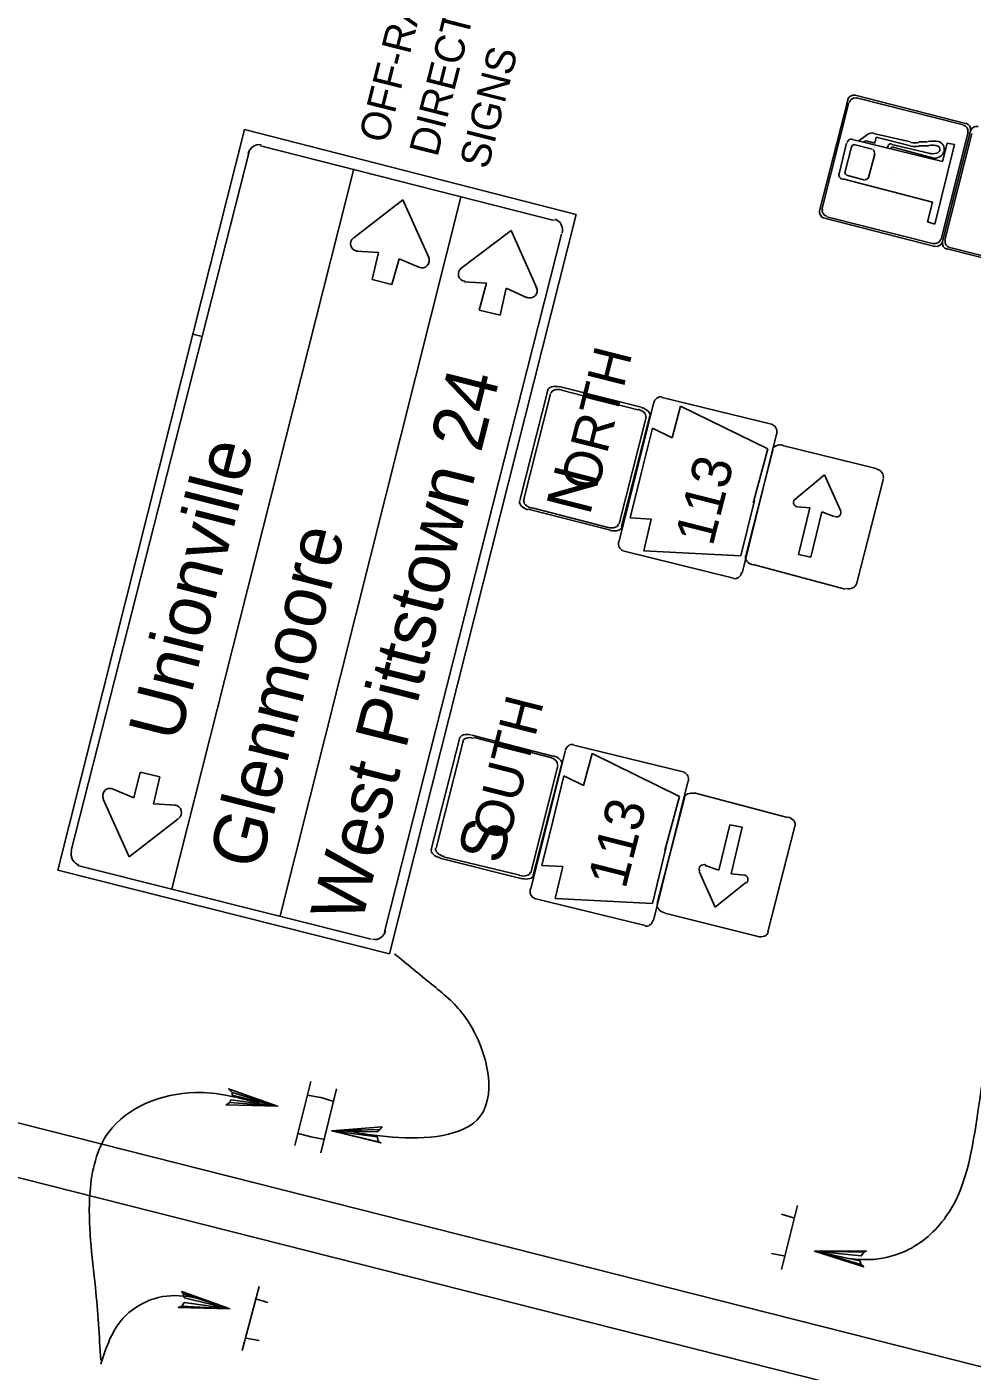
# Model space of a CAD drawing. Extents: x 644898 to 648326, y 298294 to 300670.
# Drawn here: x 647042.6 to 647138.7, y 300455.8 to 300592.6 of the extents above; entities that cross this region are included whole.
import ezdxf

# ---------------------------------------------------------------- set-up
doc = ezdxf.new("R2010")
doc.units = 0
doc.layers.add('2', color=7, linetype='Continuous')

msp = doc.modelspace()

# ---------------------------------------------------------------- linework, layer by layer
at = {"layer": '2'}
for p, q in [((647123.2, 300573.87), (647126.07, 300585.12)), ((647123.45, 300573.99), (647126.2, 300584.87)), ((647126.82, 300585.62), (647138.07, 300582.74)), ((647126.95, 300585.37), (647137.82, 300582.62)), ((647059.45, 300561.3), (647064.7, 300582.12)), ((647064.7, 300582.12), (647098.45, 300573.49)), ((647125.2, 300577.62), (647125.95, 300580.74)), ((647135.7, 300578.87), (647126.57, 300581.12)), ((647127.2, 300580.99), (647128.07, 300581.62)), ((647127.95, 300580.99), (647127.7, 300580.87)), ((647128.82, 300580.74), (647127.95, 300580.99)), ((647128.7, 300581.74), (647132.45, 300580.87)), ((647128.95, 300581.37), (647128.82, 300580.74)), ((647128.95, 300581.37), (647132.45, 300580.49)), ((647133.32, 300580.87), (647134.2, 300580.87)), ((647138.32, 300581.87), (647135.57, 300570.99)), ((647138.57, 300581.99), (647135.7, 300570.74)), ((647135.7, 300570.74), (647138.57, 300581.99)), ((647135.7, 300578.87), (647136.2, 300580.74)), ((647135.95, 300570.87), (647138.7, 300581.74)), ((647136.95, 300580.62), (647136.2, 300580.74)), ((647065.2, 300579.99), (647060.38, 300561.06)), ((647096.2, 300572.87), (647066.32, 300580.49)), ((647125.82, 300577.87), (647126.45, 300580.37)), ((647128.57, 300580.12), (647126.7, 300580.62)), ((647128.2, 300577.24), (647128.82, 300579.62)), ((647130.07, 300580.24), (647130.2, 300580.49)), ((647130.45, 300580.12), (647130.45, 300580.24)), ((647130.57, 300580.62), (647134.32, 300579.74)), ((647130.57, 300580.37), (647134.7, 300579.24)), ((647133.32, 300580.49), (647134.32, 300580.49)), ((647134.95, 300572.49), (647136.95, 300580.62)), ((647057.32, 300504.87), (647075.82, 300578.12)), ((647134.7, 300574.74), (647125.57, 300577.12)), ((647127.82, 300576.99), (647125.95, 300577.49)), ((647130.95, 300577.99), (647130.95, 300577.99)), ((647068.32, 300502.12), (647086.7, 300575.24)), ((647075.82, 300571.12), (647080.82, 300574.99)), ((647080.82, 300574.99), (647083.45, 300569.12)), ((647134.2, 300572.74), (647134.7, 300574.74)), ((647098.45, 300573.49), (647079.45, 300498.24)), ((647134.95, 300570.24), (647123.7, 300573.12)), ((647134.82, 300570.49), (647123.95, 300573.24)), ((647134.95, 300572.49), (647134.2, 300572.74)), ((647078.95, 300500.49), (647096.95, 300571.49)), ((647086.7, 300567.99), (647091.82, 300571.87)), ((647091.82, 300571.87), (647094.45, 300565.99)), ((647147.45, 300567.12), (647136.2, 300569.99)), ((647147.32, 300567.37), (647136.45, 300570.12)), ((647078.32, 300569.62), (647076.07, 300569.74)), ((647077.7, 300566.87), (647078.32, 300569.62)), ((647080.45, 300568.99), (647079.7, 300566.37)), ((647082.45, 300568.12), (647080.45, 300568.99)), ((647079.7, 300566.37), (647077.7, 300566.87)), ((647089.32, 300566.49), (647087.07, 300566.62)), ((647088.57, 300563.74), (647089.32, 300566.49)), ((647091.32, 300565.99), (647090.7, 300563.24)), ((647093.45, 300564.99), (647091.32, 300565.99)), ((647090.7, 300563.24), (647088.57, 300563.74)), ((647045.7, 300506.74), (647059.45, 300561.3)), ((647060.38, 300561.06), (647047.07, 300508.74)), ((647060.38, 300561.06), (647059.45, 300561.3)), ((647059.45, 300561.3), (647060.38, 300561.06)), ((647092.7, 300544.37), (647095.57, 300555.62)), ((647093.07, 300544.37), (647095.82, 300555.24)), ((647096.7, 300555.99), (647105.07, 300553.87)), ((647096.95, 300555.62), (647104.7, 300553.62)), ((647107.2, 300554.87), (647118.45, 300552.12)), ((647102.82, 300540.24), (647106.32, 300554.24)), ((647109.07, 300553.99), (647108.2, 300550.74)), ((647117.95, 300549.62), (647109.07, 300553.99)), ((647105.57, 300552.87), (647102.82, 300541.99)), ((647105.95, 300552.99), (647103.07, 300541.74)), ((647106.2, 300551.74), (647105.07, 300547.12)), ((647108.2, 300550.74), (647106.2, 300551.74)), ((647118.82, 300551.12), (647115.32, 300536.99)), ((647115.7, 300538.74), (647118.45, 300549.49)), ((647115.7, 300538.74), (647118.45, 300549.49)), ((647115.7, 300538.74), (647118.45, 300549.49)), ((647116.45, 300544.12), (647117.95, 300549.62)), ((647119.45, 300549.99), (647128.95, 300547.62)), ((647119.45, 300549.99), (647128.95, 300547.62)), ((647119.45, 300549.99), (647128.95, 300547.62)), ((647099.32, 300548.62), (647099.32, 300548.62)), ((647105.07, 300547.12), (647103.95, 300542.62)), ((647120.7, 300544.49), (647123.7, 300546.99)), ((647123.7, 300546.99), (647125.32, 300543.37)), ((647129.7, 300546.62), (647126.95, 300535.87)), ((647129.7, 300546.62), (647126.95, 300535.87)), ((647129.7, 300546.62), (647126.95, 300535.87)), ((647115.2, 300538.74), (647116.57, 300544.37)), ((647101.95, 300541.37), (647093.57, 300543.49)), ((647101.7, 300541.62), (647093.95, 300543.62)), ((647103.95, 300542.62), (647106.07, 300542.49)), ((647106.07, 300542.49), (647105.32, 300539.24)), ((647122.2, 300543.62), (647120.95, 300543.74)), ((647121.07, 300538.87), (647122.2, 300543.62)), ((647123.45, 300543.24), (647122.32, 300538.62)), ((647122.7, 300542.74), (647122.7, 300542.74)), ((647122.7, 300542.74), (647122.7, 300542.74)), ((647122.7, 300542.74), (647122.7, 300542.74)), ((647124.7, 300542.74), (647123.45, 300543.24)), ((647114.45, 300536.49), (647103.2, 300539.24)), ((647105.32, 300539.24), (647115.2, 300538.74)), ((647122.32, 300538.62), (647121.07, 300538.87)), ((647065.57, 300537.24), (647065.57, 300537.24)), ((647125.82, 300535.37), (647116.45, 300537.87)), ((647125.82, 300535.37), (647116.45, 300537.87)), ((647125.82, 300535.37), (647116.45, 300537.87)), ((647114.45, 300536.49), (647114.45, 300536.49)), ((647076.45, 300534.49), (647076.45, 300534.49)), ((647076.45, 300534.49), (647076.45, 300534.49)), ((647076.32, 300531.62), (647076.32, 300531.62)), ((647087.2, 300528.87), (647087.2, 300528.87)), ((647087.2, 300528.87), (647087.2, 300528.87)), ((647083.7, 300508.87), (647086.57, 300520.12)), ((647084.2, 300508.99), (647086.95, 300519.87)), ((647087.82, 300520.49), (647096.07, 300518.37)), ((647088.07, 300520.24), (647095.7, 300518.24)), ((647098.2, 300519.49), (647109.45, 300516.74)), ((647093.82, 300504.87), (647097.32, 300518.87)), ((647100.07, 300518.62), (647099.2, 300515.37)), ((647108.95, 300514.24), (647100.07, 300518.62)), ((647053.45, 300514.12), (647054.07, 300516.74)), ((647054.07, 300516.74), (647053.45, 300514.12)), ((647054.07, 300516.74), (647056.07, 300516.24)), ((647056.07, 300516.24), (647054.07, 300516.74)), ((647096.57, 300517.37), (647093.82, 300506.49)), ((647096.95, 300517.49), (647094.07, 300506.24)), ((647056.07, 300516.24), (647055.45, 300513.49)), ((647055.45, 300513.49), (647056.07, 300516.24)), ((647097.2, 300516.37), (647096.07, 300511.74)), ((647099.2, 300515.37), (647097.2, 300516.37)), ((647109.82, 300515.74), (647106.32, 300501.62)), ((647052.95, 300508.12), (647050.32, 300513.99)), ((647050.32, 300513.99), (647052.95, 300508.12)), ((647051.32, 300514.99), (647053.45, 300514.12)), ((647053.45, 300514.12), (647051.32, 300514.99)), ((647106.7, 300503.37), (647109.45, 300514.12)), ((647106.7, 300503.37), (647109.45, 300514.12)), ((647106.7, 300503.37), (647109.45, 300514.12)), ((647107.45, 300508.74), (647108.95, 300514.24)), ((647110.45, 300514.62), (647119.95, 300512.12)), ((647110.45, 300514.62), (647119.95, 300512.12)), ((647110.45, 300514.62), (647119.95, 300512.12)), ((647055.45, 300513.49), (647057.7, 300513.37)), ((647057.7, 300513.37), (647055.45, 300513.49)), ((647057.57, 300513.37), (647057.7, 300513.37)), ((647090.32, 300513.24), (647090.32, 300513.24)), ((647057.95, 300511.99), (647052.95, 300508.12)), ((647052.95, 300508.12), (647057.95, 300511.99)), ((647096.07, 300511.74), (647094.95, 300507.24)), ((647114.07, 300511.37), (647112.95, 300506.74)), ((647115.32, 300511.12), (647114.07, 300511.37)), ((647114.2, 300506.37), (647115.32, 300511.12)), ((647120.7, 300511.24), (647117.95, 300500.49)), ((647120.7, 300511.24), (647117.95, 300500.49)), ((647120.7, 300511.24), (647117.95, 300500.49)), ((647101.82, 300510.24), (647101.82, 300510.24)), ((647101.82, 300510.24), (647101.82, 300510.24)), ((647106.2, 300503.37), (647107.57, 300508.99)), ((647047.7, 300507.24), (647077.57, 300499.74)), ((647092.95, 300505.87), (647084.57, 300507.99)), ((647092.7, 300506.24), (647084.95, 300508.12)), ((647094.95, 300507.24), (647097.07, 300507.12)), ((647097.07, 300507.12), (647096.32, 300503.87)), ((647112.95, 300506.74), (647111.57, 300507.24)), ((647113.7, 300507.24), (647113.7, 300507.24)), ((647113.7, 300507.24), (647113.7, 300507.24)), ((647079.45, 300498.24), (647045.7, 300506.74)), ((647110.95, 300506.62), (647112.57, 300502.99)), ((647115.57, 300506.24), (647114.2, 300506.37)), ((647112.57, 300502.99), (647115.7, 300505.49)), ((647105.45, 300501.12), (647094.2, 300503.87)), ((647096.32, 300503.87), (647106.2, 300503.37)), ((647116.95, 300499.99), (647107.45, 300502.37)), ((647116.95, 300499.99), (647107.45, 300502.37)), ((647116.95, 300499.99), (647107.45, 300502.37)), ((647105.45, 300501.12), (647105.45, 300501.12)), ((647148.82, 300453.87), (647003.32, 300490.74)), ((647069.82, 300478.74), (647071.45, 300485.24)), ((647071.07, 300483.87), (647072.45, 300483.62)), ((647074.07, 300484.49), (647072.45, 300477.99)), ((647073.7, 300483.24), (647072.45, 300483.62)), ((647188.82, 300438.24), (647014.82, 300482.24)), ((647070.07, 300479.99), (647071.45, 300479.62)), ((647072.7, 300479.37), (647071.45, 300479.62)), ((647120.95, 300472.62), (647119.32, 300466.12)), ((647120.57, 300471.37), (647119.32, 300471.74)), ((647119.57, 300467.49), (647118.32, 300467.74)), ((647066.2, 300464.37), (647064.45, 300457.87)), ((647065.82, 300463.12), (647067.07, 300462.74)), ((647064.82, 300459.12), (647066.2, 300458.87))]:
    msp.add_line(p, q, dxfattribs=at)
for points in [[(647063.45, 300484.12), (647063.45, 300483.87), (647068.07, 300482.74), (647063.45, 300484.12), (647063.07, 300484.49), (647068.07, 300482.74), (647063.32, 300483.37), (647063.2, 300483.12), (647068.07, 300482.74), (647062.82, 300482.87), (647063.2, 300483.12)], [(647078.32, 300479.12), (647078.2, 300479.62), (647073.57, 300480.24), (647078.32, 300479.12), (647078.57, 300478.99), (647073.57, 300480.24), (647078.2, 300480.12), (647078.45, 300480.37), (647073.57, 300480.24), (647078.7, 300480.62), (647078.45, 300480.37)], [(647127.45, 300466.62), (647127.32, 300466.99), (647122.7, 300467.99), (647127.45, 300466.62), (647127.7, 300466.37), (647122.7, 300467.99), (647127.45, 300467.49), (647127.7, 300467.87), (647122.7, 300467.99), (647127.95, 300467.99), (647127.7, 300467.87)], [(647058.45, 300463.62), (647058.57, 300463.24), (647063.2, 300462.12), (647058.45, 300463.62), (647058.32, 300463.87), (647063.2, 300462.12), (647058.57, 300462.74), (647058.32, 300462.37), (647063.2, 300462.12), (647057.95, 300462.24), (647058.32, 300462.37)]]:
    msp.add_lwpolyline(points, dxfattribs=at)
for centre, radius, start, end in [((647126.69, 300584.99), 0.645, 75.7754, 165.7754), ((647126.83, 300584.76), 0.597, 75.7754, 165.7754), ((647137.71, 300582), 0.597, 345.7754, 75.7754), ((647137.94, 300582.14), 0.645, 345.7754, 75.7754), ((647139.19, 300581.82), 0.645, 75.7754, 165.7754), ((647126.47, 300580.67), 0.486, 83.6778, 164.7031), ((647128.59, 300580.79), 0.991, 81.3158, 122.9841), ((647132.9, 300583.76), 2.98, 262.3862, 278.0519), ((647134.78, 300578.28), 2.68, 78.1727, 101.1253), ((647135.06, 300580.11), 0.84, 344.9893, 71.1198), ((647126.71, 300580.3), 0.274, 92.8615, 169.1523), ((647128.41, 300579.75), 0.392, 341.4902, 59.3145), ((647130.46, 300580.37), 0.318, 75.201, 153.6335), ((647130.54, 300580.24), 0.0771, 64.9719, 167.615), ((647132.9, 300583.76), 3.35, 262.3862, 278.0519), ((647134.67, 300578.96), 1.59, 68.02, 103.4387), ((647134.71, 300581.2), 1.53, 256.8807, 285.2561), ((647134.96, 300580.18), 0.953, 254.9902, 342.4176), ((647135.07, 300580.11), 0.381, 275.7441, 58.872), ((647125.59, 300577.5), 0.415, 157.4008, 262.3628), ((647126.03, 300577.75), 0.249, 154.0614, 244.0323), ((647127.88, 300577.35), 0.314, 262.0164, 342.4308), ((647124.07, 300573.88), 0.597, 165.7754, 255.7754), ((647123.84, 300573.74), 0.645, 165.7754, 255.7754), ((647076.23, 300570.5), 0.745, 125.638, 266.3035), ((647134.95, 300571.12), 0.597, 255.7754, 345.7754), ((647135.09, 300570.88), 0.645, 255.7754, 345.7754), ((647136.34, 300570.57), 0.645, 165.7754, 255.7754), ((647136.57, 300570.71), 0.597, 165.7754, 255.7754), ((647082.76, 300568.8), 0.745, 244.0264, 27.9331), ((647087.2, 300567.43), 0.745, 125.638, 266.3035), ((647093.73, 300565.73), 0.745, 244.0264, 27.9331), ((647121, 300544.19), 0.45, 126.1169, 265.3481), ((647124.93, 300543.16), 0.45, 247.2918, 24.1455), ((647051.02, 300514.33), 0.745, 64.0264, 207.9331), ((647051.02, 300514.33), 0.745, 64.0264, 207.9331), ((647057.55, 300512.63), 0.745, 305.638, 86.3035), ((647057.55, 300512.63), 0.745, 305.638, 86.3035), ((647111.42, 300506.86), 0.46, 64.0256, 207.9322), ((647115.46, 300505.81), 0.46, 305.6371, 86.3026)]:
    msp.add_arc(centre, radius, start, end, dxfattribs=at)
for centre, major_axis, ratio, start_param, end_param in [((647066.1, 300579.41), (-0.29, -1.16), 0.890186, 3.141593, 4.712389), ((647095.98, 300571.84), (0.29, 1.16), 0.890186, 4.712389, 6.283185), ((647096.58, 300555.32), (-1.04, 0.26), 0.6, 4.712389, 6.283185), ((647096.84, 300555.05), (-0.964, 0.244), 0.6, 4.712389, 6.283185), ((647106.96, 300554.13), (-0.198, -0.782), 0.8, 3.141593, 4.712389), ((647104.56, 300553.1), (-0.964, 0.244), 0.6, 3.141593, 4.712389), ((647104.92, 300553.21), (-1.04, 0.26), 0.6, 3.141593, 4.712389), ((647118.22, 300551.28), (0.198, 0.782), 0.8, 4.712389, 6.283185), ((647119.31, 300549.3), (-0.903, 0.229), 0.769266, 4.712389, 6.283185), ((647119.31, 300549.3), (-0.903, 0.229), 0.769266, 4.712389, 6.283185), ((647119.31, 300549.3), (-0.903, 0.229), 0.769266, 4.712389, 6.283185), ((647128.79, 300546.9), (-0.903, 0.229), 0.769266, 3.141593, 4.712389), ((647128.79, 300546.9), (-0.903, 0.229), 0.769266, 3.141593, 4.712389), ((647128.79, 300546.9), (-0.903, 0.229), 0.769266, 3.141593, 4.712389), ((647093.73, 300544.06), (1.04, -0.26), 0.6, 3.141593, 4.712389), ((647094.08, 300544.17), (0.964, -0.244), 0.6, 3.141593, 4.712389), ((647101.8, 300542.21), (0.964, -0.244), 0.6, 4.712389, 6.283185), ((647102.07, 300541.95), (1.04, -0.26), 0.6, 4.712389, 6.283185), ((647103.4, 300540.07), (-0.198, -0.782), 0.8, 4.712389, 6.283185), ((647116.58, 300538.53), (0.903, -0.229), 0.769266, 3.141593, 4.712389), ((647116.58, 300538.53), (0.903, -0.229), 0.769266, 3.141593, 4.712389), ((647116.58, 300538.53), (0.903, -0.229), 0.769266, 3.141593, 4.712389), ((647114.65, 300537.21), (0.198, 0.782), 0.8, 3.141593, 4.712389), ((647126.06, 300536.13), (0.903, -0.229), 0.769266, 4.712389, 6.283185), ((647126.06, 300536.13), (0.903, -0.229), 0.769266, 4.712389, 6.283185), ((647126.06, 300536.13), (0.903, -0.229), 0.769266, 4.712389, 6.283185), ((647087.6, 300519.89), (-1.04, 0.26), 0.6, 4.712389, 6.283185), ((647087.86, 300519.62), (-0.964, 0.244), 0.6, 4.712389, 6.283185), ((647097.96, 300518.76), (-0.198, -0.782), 0.8, 3.141593, 4.712389), ((647095.58, 300517.67), (-0.964, 0.244), 0.6, 3.141593, 4.712389), ((647095.94, 300517.77), (-1.04, 0.26), 0.6, 3.141593, 4.712389), ((647109.22, 300515.91), (0.198, 0.782), 0.8, 4.712389, 6.283185), ((647110.33, 300513.87), (-0.903, 0.229), 0.769266, 4.712389, 6.283185), ((647110.33, 300513.87), (-0.903, 0.229), 0.769266, 4.712389, 6.283185), ((647110.33, 300513.87), (-0.903, 0.229), 0.769266, 4.712389, 6.283185), ((647119.81, 300511.47), (-0.903, 0.229), 0.769266, 3.141593, 4.712389), ((647119.81, 300511.47), (-0.903, 0.229), 0.769266, 3.141593, 4.712389), ((647119.81, 300511.47), (-0.903, 0.229), 0.769266, 3.141593, 4.712389), ((647048.14, 300508.46), (-0.29, -1.16), 0.890186, 4.712389, 6.283185), ((647084.75, 300508.63), (1.04, -0.26), 0.6, 3.141593, 4.712389), ((647085.11, 300508.74), (0.964, -0.244), 0.6, 3.141593, 4.712389), ((647092.82, 300506.78), (0.964, -0.244), 0.6, 4.712389, 6.283185), ((647093.09, 300506.52), (1.04, -0.26), 0.6, 4.712389, 6.283185), ((647094.4, 300504.69), (-0.198, -0.782), 0.8, 4.712389, 6.283185), ((647107.6, 300503.1), (0.903, -0.229), 0.769266, 3.141593, 4.712389), ((647107.6, 300503.1), (0.903, -0.229), 0.769266, 3.141593, 4.712389), ((647107.6, 300503.1), (0.903, -0.229), 0.769266, 3.141593, 4.712389), ((647105.65, 300501.84), (0.198, 0.782), 0.8, 3.141593, 4.712389), ((647078.02, 300500.88), (0.29, 1.16), 0.890186, 3.141593, 4.712389), ((647117.08, 300500.7), (0.903, -0.229), 0.769266, 4.712389, 6.283185), ((647117.08, 300500.7), (0.903, -0.229), 0.769266, 4.712389, 6.283185), ((647117.08, 300500.7), (0.903, -0.229), 0.769266, 4.712389, 6.283185)]:
    msp.add_ellipse(centre, major_axis=major_axis, ratio=ratio, start_param=start_param, end_param=end_param, dxfattribs=at)
for points in [[(647153.07, 300562.49), (647149.57, 300528.37), (647141.82, 300497.49), (647139.2, 300481.37), (647136.07, 300471.49), (647131.95, 300467.99), (647128.2, 300467.12), (647122.7, 300467.99)], [(647079.95, 300498.24), (647083.73, 300495.15), (647087, 300492), (647088.69, 300481.71), (647079.79, 300479.59), (647074.95, 300480.24)], [(647050.07, 300456.87), (647049.53, 300464.27), (647048.98, 300474.02), (647050.86, 300480.07), (647059.63, 300484.12), (647066.23, 300483.04)], [(647050.07, 300456.49), (647052.32, 300461.12), (647056.36, 300463.35), (647063.2, 300462.12)]]:
    msp.add_spline(points, degree=3, dxfattribs=at)

# ---------------------------------------------------------------- texts
for s, height, rotation, p in [('DIRECTIONAL', 3, 75.7789, (647084.32, 300579.24)), ('OFF-RAMP', 3, 75.7789, (647079.2, 300580.62)), ('SIGNS', 3, 75.7789, (647089.45, 300577.99)), ('ORTH', 3.875, 75.7783, (647100.57, 300545.12)), ('West Pittstown 24', 5.3752, 75.7788, (647076.57, 300501.12)), ('Unionville', 5.375, 75.7788, (647058.03, 300519.63)), ('113', 4, 75.7777, (647112.32, 300539.62)), ('N', 4.63, 75.7284, (647099.82, 300542.74)), ('Glenmoore   ', 5.3752, 75.7788, (647066.22, 300506.62)), ('OUTH', 3.875, 75.7783, (647091.57, 300509.62)), ('113', 4, 75.7777, (647103.45, 300504.74)), ('S', 4.63, 75.7284, (647090.82, 300507.24))]:
    msp.add_text(s, height=height, rotation=rotation, dxfattribs=at).set_placement(p)

doc.saveas('drawing.dxf')
